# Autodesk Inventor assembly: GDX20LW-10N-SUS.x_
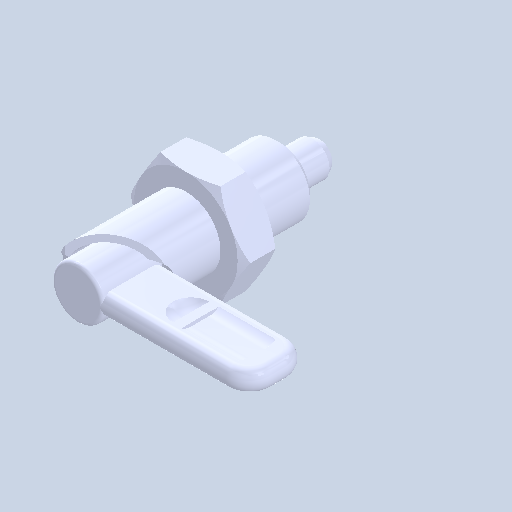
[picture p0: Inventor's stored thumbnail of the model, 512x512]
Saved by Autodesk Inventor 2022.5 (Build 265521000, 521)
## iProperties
Created: 2024-06
Part Number: GDX20LW-10N-SUS.x_
Document SubType Name: Assembly
Designer: ImaoCorp
Author: ImaoCorp
Sending System: SOLIDWORKS 2022-2022290
MC: AMD64
MC_MODEL: Intel64 Family 6 Model 60 Stepping 3, GenuineIntel
OS: Windows_NT
FRU: Parasolid Version 33.1, build 260,  4-25-2022
FORMAT: text
GUISE: transmit
KEY: FILEGDX20LW-10N-SUS.x_t
DATE: Wed Jun 12 09:33:01 2024
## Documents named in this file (4)
- Y:\5.更新分\2024年対応\xxxx_GDX\データ_imao品番\gdx20lw-10n-sus\GDX20LW-10N-SUS.x_.iam
- Y:\5.更新分\2024年対応\xxxx_GDX\データ_imao品番\gdx20lw-10n-sus\GDX20LW-10N-SUS_01.ipt
- Y:\5.更新分\2024年対応\xxxx_GDX\データ_imao品番\gdx20lw-10n-sus\GDX20LW-10N-SUS_02.ipt
- Y:\5.更新分\2024年対応\xxxx_GDX\データ_imao品番\gdx20lw-10n-sus\GDX20LW-10N-SUS_03.ipt
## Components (3 placed, 3 different names)
1. GDX20LW-10N-SUS_01
2. GDX20LW-10N-SUS_02
3. GDX20LW-10N-SUS_03
